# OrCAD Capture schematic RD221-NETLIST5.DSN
size A3
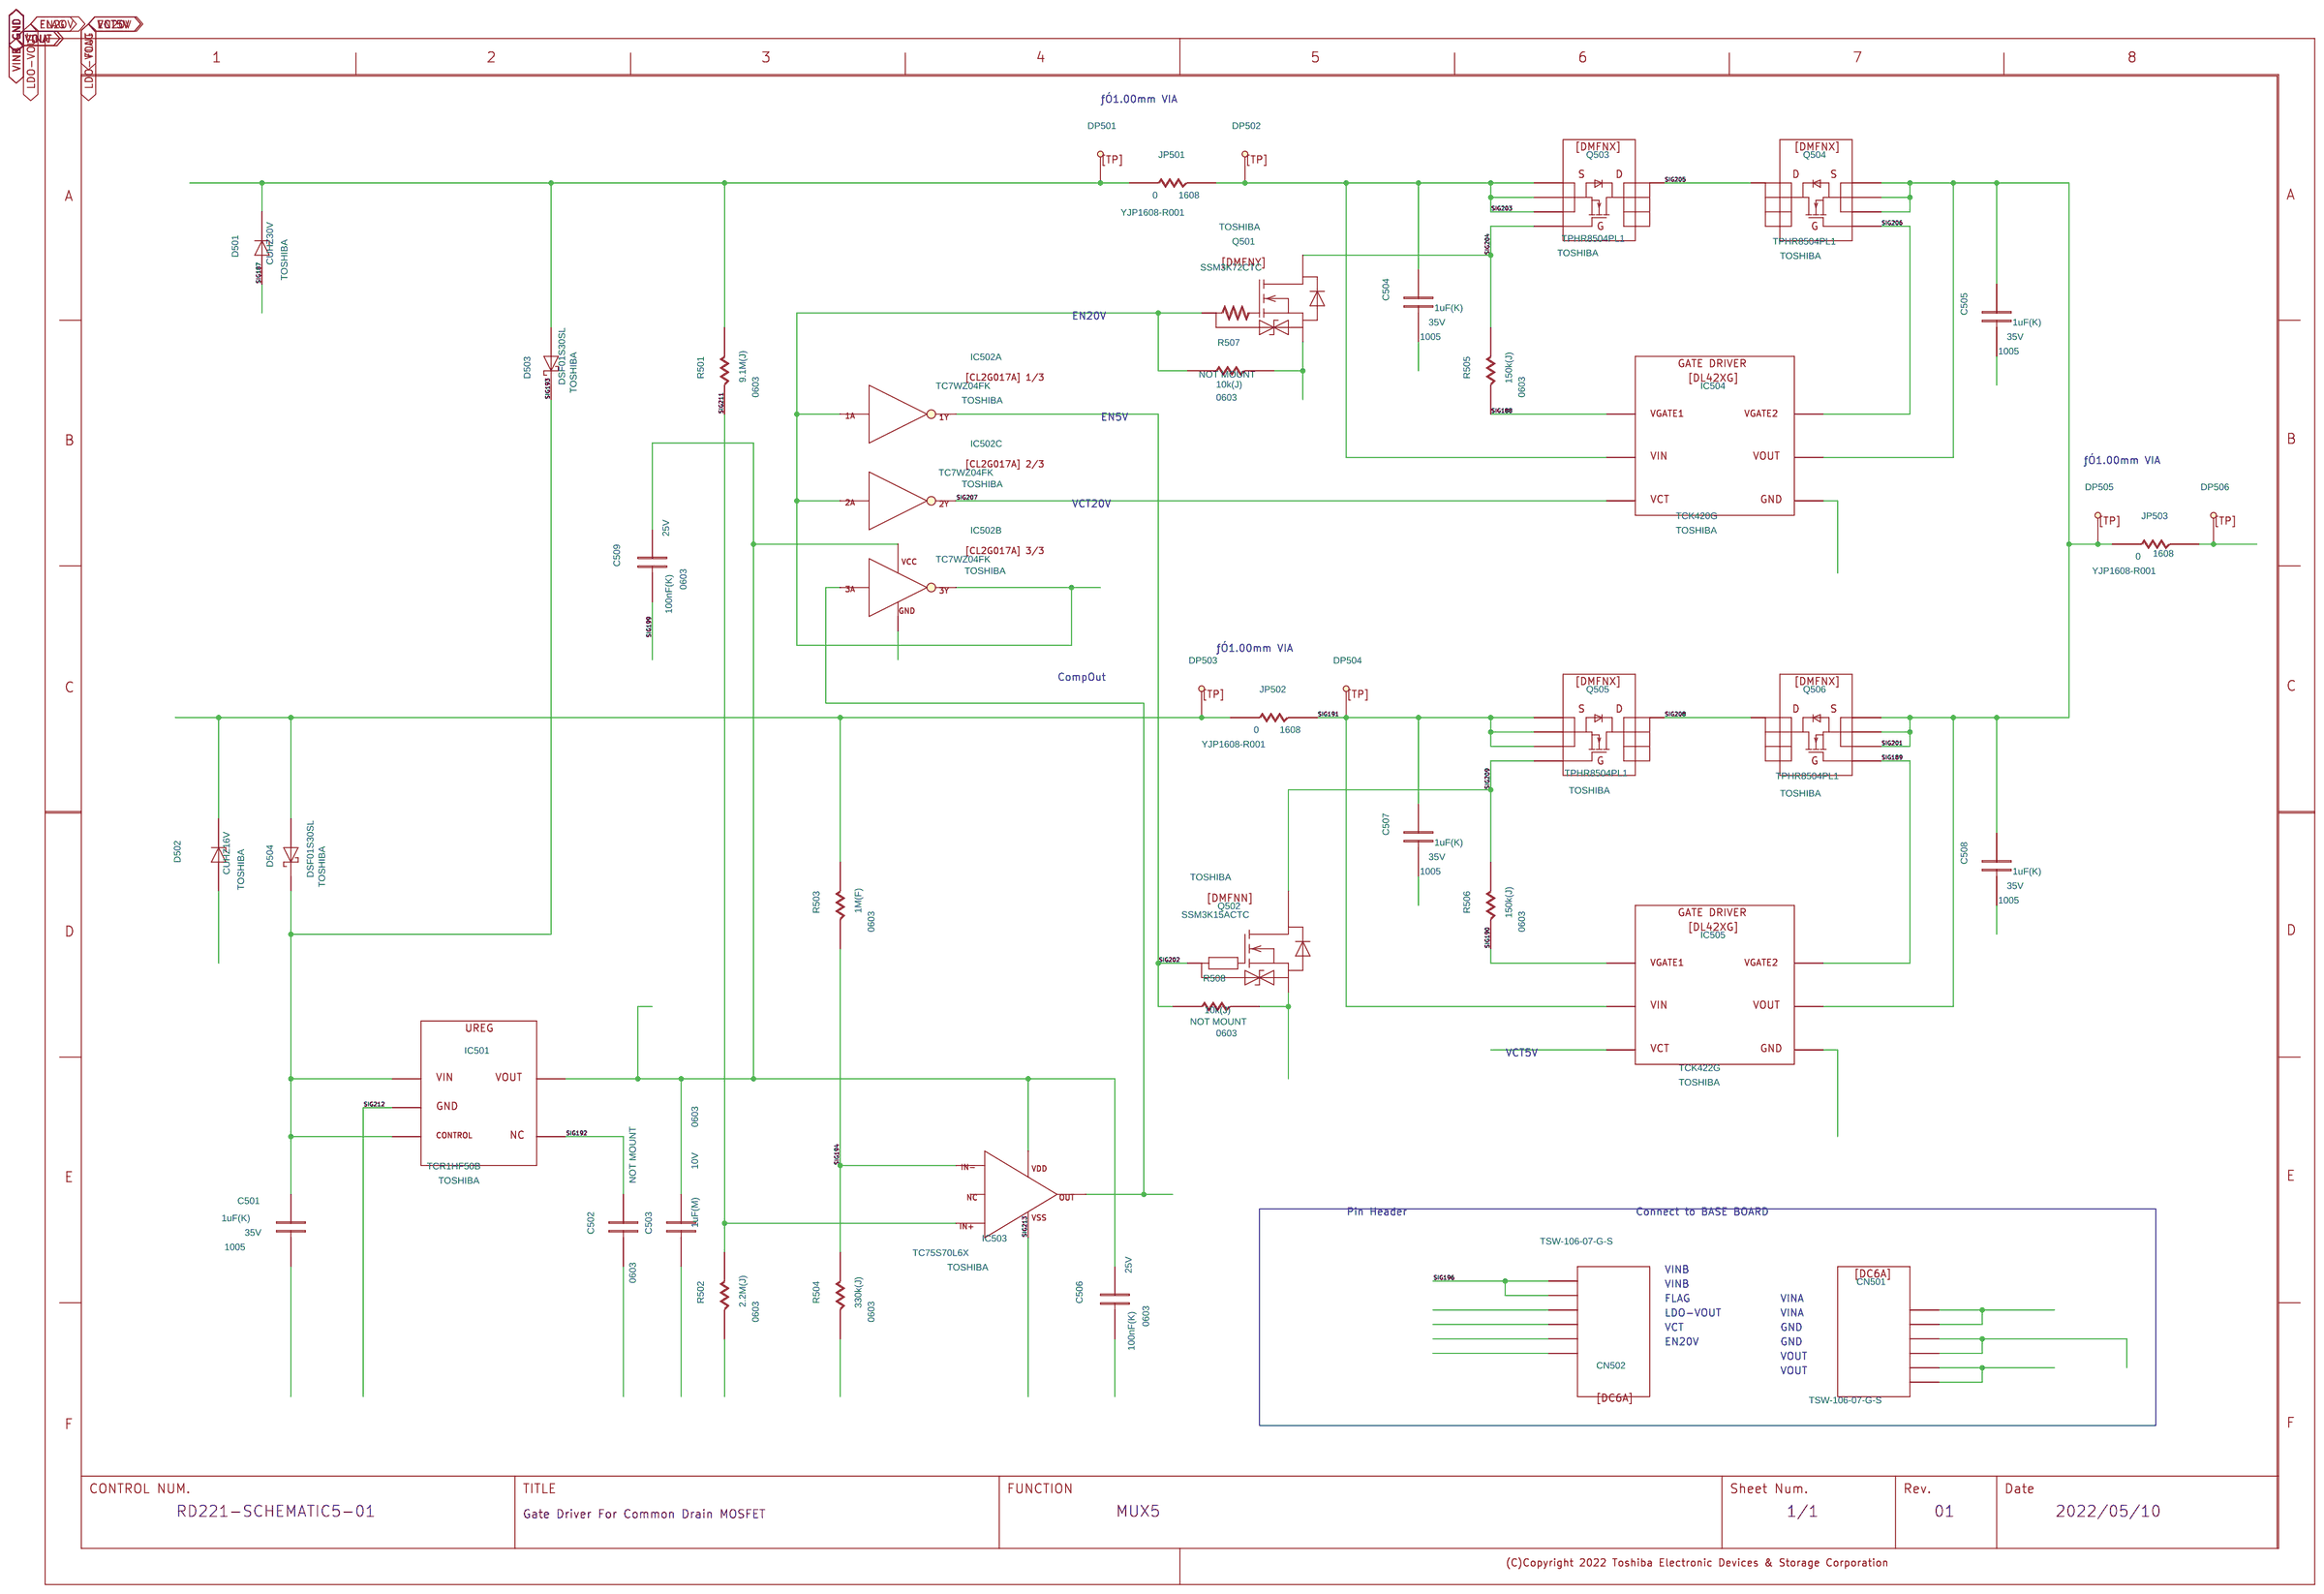
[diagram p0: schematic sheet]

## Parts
C501  DC
C502  DC
C503  DC
C504  DC
C505  DC
C506  DC
C507  DC
C508  DC
C509  DC
CN501  DC6A
CN502  DC6A
D501  DZD
D502  DZD
D503  DSBD
D504  DSBD
DP501  DTP
DP502  DTP
DP503  DTP
DP504  DTP
DP505  DTP
DP506  DTP
IC501  DL1HFXX
IC502  TC7WZ04FK_1  (sections A,B,C)
IC503  TC75S70L6X
IC504  DL42XG
IC505  DL42XG
JP501  DR
JP502  DR
JP503  DR
Q501  DMFNY
Q502  DMFNN
Q503  DMFNX
Q504  DMFNX
Q505  DMFNX
Q506  DMFNX
R501  DR
R502  DR
R503  DR
R504  DR
R505  DR
R506  DR
R507  DR
R508  DR
U?#1  WAKU_DEF100

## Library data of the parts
C501 C504 C505 C507 C508 = DC: COMP: DP0000016125; COMPONENTNAME: DP0000016125_package; FUNCN: DP0000016125; GCOUNT: 1; MAXGCOUNT: 1; OUMEPARTTYPE: C; SIZECODESMD: 1005; VAL1: 1uF(K); VAL2: 35V; VAL3: GRM155R6YA105KE11D
C502 = DC: COMP: DP0007093000; COMPONENTNAME: DP0007093000_package; FUNCN: DP0007093000; GCOUNT: 1; MAXGCOUNT: 1; NOTMOUNT: NOT MOUNT; OUMEPARTTYPE: C; SIZECODESMD: 0603; VAL1: 1uF(M); VAL2: 10V; VAL3: GRM033R61A105ME15D
C503 = DC: COMP: DP0007093000; COMPONENTNAME: DP0007093000_package; FUNCN: DP0007093000; GCOUNT: 1; MAXGCOUNT: 1; OUMEPARTTYPE: C; SIZECODESMD: 0603; VAL1: 1uF(M); VAL2: 10V; VAL3: GRM033R61A105ME15D
C506 C509 = DC: COMP: DP0000015403; COMPONENTNAME: DP0000015403_package; FUNCN: DP0000015403; GCOUNT: 1; MAXGCOUNT: 1; OUMEPARTTYPE: C; SIZECODESMD: 0603; VAL1: 100nF(K); VAL2: 25V; VAL3: GRM033R61E104KE14D
CN501 CN502 = DC6A: COMP: DP0010563000; COMPONENTNAME: DP0010563000_package; FUNCN: DP0010563000; GCOUNT: 1; MAXGCOUNT: 1; OUMEPARTTYPE: CN; VAL3: TSW-106-07-G-S
D501 = DZD: COMP: DP0010557000; COMPONENTNAME: DP0010557000_package; FUNCN: DP0010557000; GCOUNT: 1; MAXGCOUNT: 1; OUMEPARTTYPE: D; USERCOMPTEXT3: TOSHIBA; VAL1: CUHZ30V; VAL3: CUHZ30V
D502 = DZD: COMP: DP0010580000; COMPONENTNAME: DP0010580000_package; FUNCN: DP0010580000; GCOUNT: 1; MAXGCOUNT: 1; OUMEPARTTYPE: D; USERCOMPTEXT3: TOSHIBA; VAL1: CUHZ16V; VAL3: CUHZ16V
D503 D504 = DSBD: COMP: DP0010560000; COMPONENTNAME: DP0010560000_package; FUNCN: DP0010560000; GCOUNT: 1; MAXGCOUNT: 1; OUMEPARTTYPE: D; USERCOMPTEXT3: TOSHIBA; VAL1: DSF01S30SL; VAL3: DSF01S30SL
DP501-DP506 = DTP: COMP: DP9000817000; COMPONENTNAME: DP9000817000_package; FUNCN: DP9000817000; GCOUNT: 1; MAXGCOUNT: 1; NOTMOUNT: NOT MOUNT; OUMEPARTTYPE: TP
IC501 = DL1HFXX: COMP: DP0010585000; COMPONENTNAME: DP0010585000_package; FUNCN: DP0010585000; USERCOMPTEXT3: TOSHIBA; VAL1: TCR1HF50B; VAL3: TCR1HF50B
IC502 = TC7WZ04FK_1: COMP: DP0001429000; CaptureCellPackProp: TC7WZ04FK_1A; FUNCN: DP0001429000_1; USERCOMPTEXT3: TOSHIBA; VAL1: TC7WZ04FK; VAL3: TC7WZ04FK
IC503 = TC75S70L6X: COMP: DP0010561000; COMPONENTNAME: DP0010561000; FUNCN: DP0010561000; USERCOMPTEXT3: TOSHIBA
IC504 = DL42XG: COMP: DP0010596000; COMPONENTNAME: DP0010596000_package; FUNCN: DP0010596000; GCOUNT: 1; MAXGCOUNT: 1; OUMEPARTTYPE: IC; SAVEAREA0: 0,-2569,38100,25362; UPDATEDATE: 2021/11/09; UPDATETIME: 14:52:41; UPDATEUSER: t5459927; USERCOMPTEXT3: TOSHIBA; VAL1: TCK420G; VAL3: TCK420G
IC505 = DL42XG: COMP: DP0010597000; COMPONENTNAME: DP0010597000_package; FUNCN: DP0010597000; GCOUNT: 1; MAXGCOUNT: 1; OUMEPARTTYPE: IC; SAVEAREA0: -5715,0,43876,22860; UPDATEDATE: 2021/11/09; UPDATETIME: 13:49:24; UPDATEUSER: t5459927; USERCOMPTEXT3: TOSHIBA; VAL1: TCK422G; VAL3: TCK422G
JP501-JP503 = DR: COMP: DP0001376000; COMPCOMMENT: 0; COMPONENTNAME: DP0001376000_package; FUNCN: DP0001376000; GCOUNT: 1; MAXGCOUNT: 1; OUMEPARTTYPE: R; SIZECODESMD: 1608; VAL1: 200u(X); VAL2: 30mW; VAL3: YJP1608-R001
Q501 = DMFNY: COMP: DP0010564000; COMPONENTNAME: DP0010564000_package; FUNCN: DP0010564000; GCOUNT: 1; MAXGCOUNT: 1; OUMEPARTTYPE: Q; SAVEAREA0: -2026,0,24927,17780; UPDATEDATE: 2019/01/15; UPDATETIME: 15:53:55; UPDATEUSER: e1023210; USERCOMPTEXT3: TOSHIBA; VAL1: SSM3K72CTC; VAL3: SSM3K72CTC
Q502 = DMFNN: COMP: DP0010513000; COMPONENTNAME: DP0010513000_package; DEVICE: RN4905; DEVICENAME: RN49A1FE(TE85L); FUNCN: DP0010513000; FUNCTION: PNP&NPN_PCT; GCOUNT: 1; HETERO: RN4905_1,RN4905_2; LEVEL: STD; MAXGCOUNT: 1; OUMEPARTTYPE: Q; P/D_NUM: TOSHIBA; PARTS: 1; PKG_TYPE: 2-2J1A; SAVEAREA0: -41191,-19664,61952,27881; UPDATEDATE: 2021/11/11; UPDATETIME: 08:00:04; UPDATEUSER: t5459927; USERCOMPTEXT3: TOSHIBA; VAL1: SSM3K15ACTC; VAL3: SSM3K15ACTC
Q503-Q506 = DMFNX: COMP: DP0010567000; COMPONENTNAME: DP0010567000_package; FUNCN: DP0010567000; GCOUNT: 1; MAXGCOUNT: 1; OUMEPARTTYPE: Q; USERCOMPTEXT3: TOSHIBA; VAL1: TPHR8504PL1; VAL3: TPHR8504PL1
R501 = DR: COMP: DP0000151167; COMPONENTNAME: DP0000151167; FUNCN: DP0000151167; GCOUNT: 1; MAXGCOUNT: 1; OUMEPARTTYPE: R; SIZECODESMD: 0603; VAL1: 9.1M(J); VAL2: 50mW; VAL3: ERJ1GNJ915C
R502 = DR: COMP: DP0000151152; COMPONENTNAME: DP0000151152; FUNCN: DP0000151152; GCOUNT: 1; MAXGCOUNT: 1; OUMEPARTTYPE: R; SIZECODESMD: 0603; VAL1: 2.2M(J); VAL2: 50mW; VAL3: ERJ1GNJ225C
R503 = DR: COMP: DP0000152120; COMPONENTNAME: DP0000152120; FUNCN: DP0000152120; GCOUNT: 1; MAXGCOUNT: 1; OUMEPARTTYPE: R; SIZECODESMD: 0603; VAL1: 1M(F); VAL2: 50mW; VAL3: ERJ1GNF1004C
R504 = DR: COMP: DP0000151132; COMPONENTNAME: DP0000151132; FUNCN: DP0000151132; GCOUNT: 1; MAXGCOUNT: 1; OUMEPARTTYPE: R; SIZECODESMD: 0603; VAL1: 330k(J); VAL2: 50mW; VAL3: ERJ1GNJ334C
R505 R506 = DR: COMP: DP0000155124; COMPONENTNAME: DP0000155124; FUNCN: DP0000155124; GCOUNT: 1; MAXGCOUNT: 1; OUMEPARTTYPE: R; SIZECODESMD: 0603; VAL1: 150k(J); VAL2: 50mW; VAL3: RK73B1HTTC154J
R507 R508 = DR: COMP: DP0002867000; COMPONENTNAME: DP0002867000_package; FUNCN: DP0002867000; GCOUNT: 1; MAXGCOUNT: 1; NOTMOUNT: NOT MOUNT; OUMEPARTTYPE: R; SIZECODESMD: 0603; VAL1: 10k(J); VAL2: 50mW; VAL3: RK73B1HTTCM103J
U?#1 = WAKU_DEF100: DATE: 2022/05/10; DRAWINGNUMBER: RD221-SCHEMATIC5-01; FUNCTION: MUX5; REVISION: 01; SAVEAREA0: 148187,-66180,486823,89919; SAVECOUNT: 6; SHEETNUMBER: 1/1; TITLE: Gate Driver For Common Drain MOSFET; UPDATEDATE: 2022/05/17; UPDATETIME: 07:14:33

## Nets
GND: C501.2 C502.2 C503.2 C504.2 C505.2 C506.2 C507.2 C508.2 C509.2 CN501.3 CN501.4 D501.A D502.A IC501.2 IC502.4 IC503.2 IC504.B2 IC505.B2 Q501.S Q502.S R502.2 R504.2 R507.2 R508.2
VINA: CN501.1 CN501.2 D501.C D503.A DP501.1 JP501.1 R501.1
VINB: CN502.5 CN502.6 D502.C D504.A DP503.1 JP502.1 R503.1
EN20V: CN502.1 IC502.1 IC502.2 IC502.3 Q501.G R507.1
FLAG: CN502.4 IC502.6 IC503.1
LDO-VOUT: C503.1 C506.1 C509.1 CN502.3 IC501.5 IC502.8 IC503.6
SIG188: IC504.A1 R505.2
SIG189: IC505.B1 Q506.4
SIG190: IC505.A1 R506.2
SIG191: C507.1 DP504.1 IC505.A2 JP502.2 Q505.1 Q505.2 Q505.3
SIG192: C502.1 IC501.4
SIG193: C501.1 D503.C D504.C IC501.1 IC501.3
SIG194: IC503.4 R503.2 R504.1
SIG201: C505.1 C508.1 DP505.1 IC504.C1 IC505.C1 JP503.1 Q504.1 Q504.2 Q504.3 Q506.1 Q506.2 Q506.3
SIG202: IC502.7 Q502.G R508.1
SIG203: C504.1 DP502.1 IC504.A2 JP501.2 Q503.1 Q503.2 Q503.3
SIG204: Q501.D Q503.4 R505.1
SIG205: Q503.5 Q504.5
SIG206: IC504.B1 Q504.4
SIG207: IC502.5 IC504.C2
SIG208: Q505.5 Q506.5
SIG209: Q502.D Q505.4 R506.1
SIG211: IC503.3 R501.2 R502.1
VCT5V: CN502.2 IC505.C2
VOUT: CN501.5 CN501.6 DP506.1 JP503.2

Not connected (* = marked no-connect by the designer): IC503 5

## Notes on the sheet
- ƒÓ1.00mm VIA
- EN20V
- EN5V
- ƒÓ1.00mm VIA
- VCT20V
- ƒÓ1.00mm VIA
- CompOut
- VCT5V
- Pin Header
- Connect to BASE BOARD
- VINB
- VINB
- FLAG
- VINA
- LDO-VOUT
- VINA
- VCT
- GND
- EN20V
- GND
- VOUT
- VOUT
